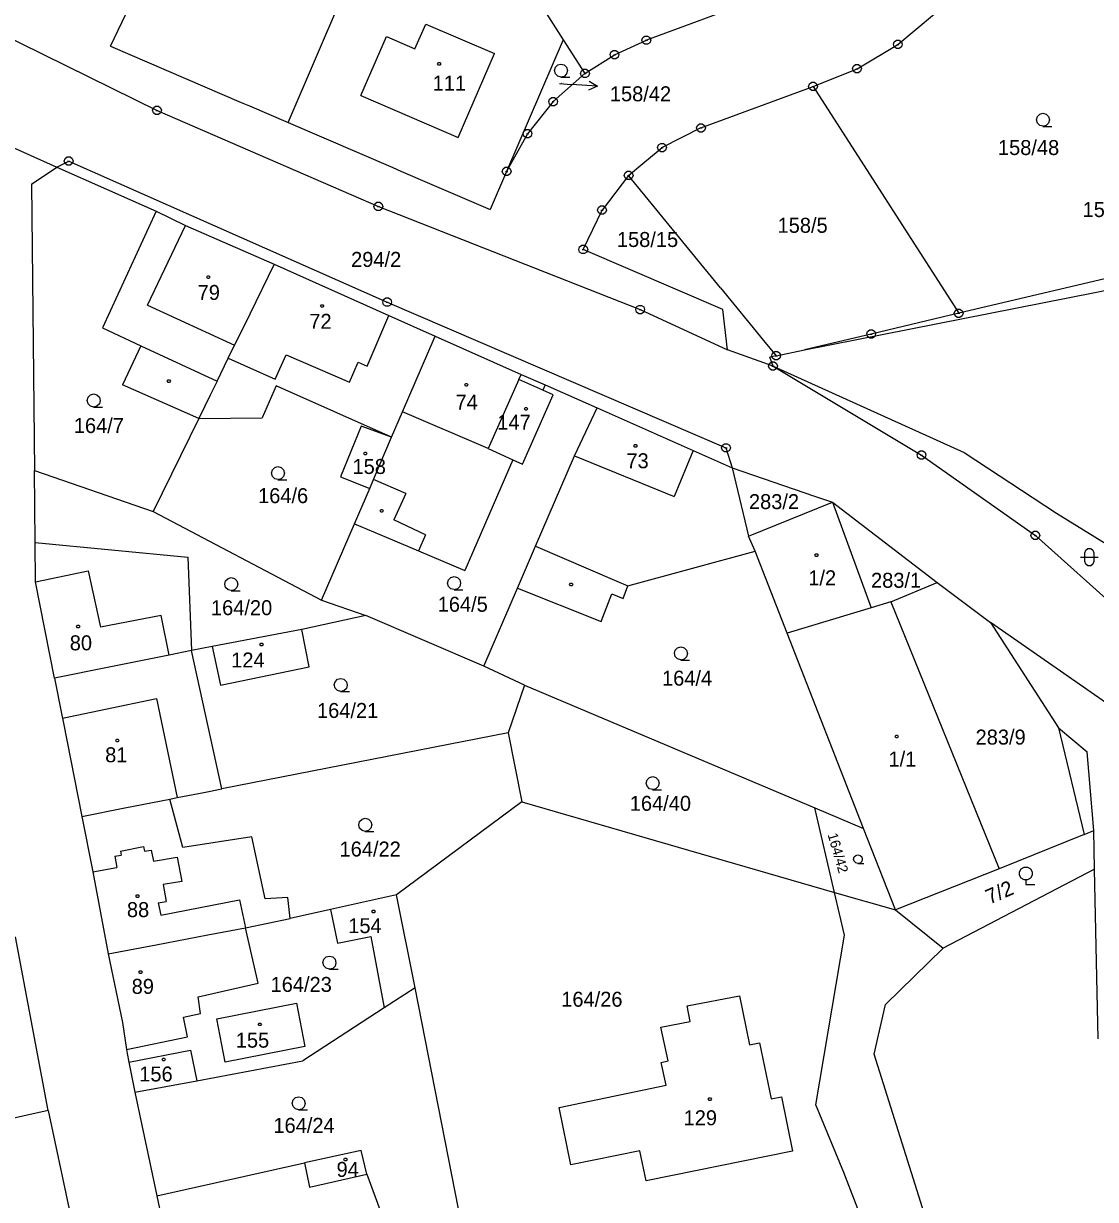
# Model space of a CAD drawing. Extents: x -780000 to -777378, y -1011169 to -1009297.
# Drawn here: x -779372 to -779250.3, y -1010258.1 to -1010124.6 of the extents above; entities that cross this region are included whole.
import ezdxf

# ---------------------------------------------------------------- set-up
doc = ezdxf.new("R2010")
doc.units = 0
for name, color, linetype in [('Default', 7, 'Continuous'), ('KN_HRANICE', 7, 'Continuous'), ('KN_KULTURY', 7, 'Continuous'), ('KN_PARCELY', 7, 'Continuous'), ('KN_SLUCKY', 7, 'Continuous')]:
    doc.layers.add(name, color=color, linetype=linetype)

# ---------------------------------------------------------------- blocks, each defined once
blk = doc.blocks.new('304')
at = {"layer": 'Default'}
blk.add_lwpolyline([(0, 0), (-0.38, 0.1), (-0.65, 0.37), (-0.75, 0.74), (-0.65, 1.11), (-0.38, 1.38), (-0.01, 1.48), (0.36, 1.38), (0.63, 1.11), (0.73, 0.73), (0.63, 0.35), (0.36, 0.08), (-0.02, -0.02), (0.98, -0.02)], dxfattribs=at)
blk = doc.blocks.new('305')
at = {"layer": 'Default'}
blk.add_lwpolyline([(0, 0.53), (-0.19, 0.53), (-0.53, 0.72), (-0.72, 1.06), (-0.72, 1.45), (-0.53, 1.79), (-0.19, 1.98), (0.2, 1.98), (0.54, 1.79), (0.73, 1.45), (0.73, 1.06), (0.54, 0.72), (0.2, 0.53), (0.01, 0.53), (0.01, 0), (1.01, 0)], dxfattribs=at)
blk = doc.blocks.new('316')
at = {"layer": 'Default'}
for points in [[(-0.5, 1.5), (-0.4, 1.79), (-0.15, 1.97), (0.16, 1.97), (0.41, 1.79), (0.51, 1.5), (0.51, 0.5), (0.41, 0.21), (0.16, 0.03), (-0.15, 0.03), (-0.4, 0.21), (-0.5, 0.5), (-0.5, 1.5)], [(-1, 1), (0.27, 1), (1, 1)]]:
    blk.add_lwpolyline(points, dxfattribs=at)
blk = doc.blocks.new('10292')
at = {"layer": 'Default'}
blk.add_line((0, 3), (0, 0), dxfattribs=at)
blk.add_lwpolyline([(-0.5, 2), (0, 3), (0.5, 2)], dxfattribs=at)
blk = doc.blocks.new('402')
at = {"layer": 'Default'}
blk.add_lwpolyline([(0.09, 0.15), (0.18, 0), (0.09, -0.15), (-0.09, -0.15), (-0.18, 0), (-0.09, 0.15), (0.09, 0.15)], dxfattribs=at)
blk = doc.blocks.new('105')
at = {"layer": 'Default'}
blk.add_line((-0.12, 0), (0.12, 0), dxfattribs=at)
blk.add_lwpolyline([(0.15, 0.48), (0.4, 0.3), (0.5, 0.01), (0.4, -0.28), (0.15, -0.46), (-0.16, -0.46), (-0.41, -0.28), (-0.51, 0.01), (-0.41, 0.3), (-0.16, 0.48), (0.15, 0.48)], dxfattribs=at)

msp = doc.modelspace()

# ---------------------------------------------------------------- linework, layer by layer
at = {"layer": 'KN_HRANICE'}
for p, q in [((-779362.17, -1010127.2), (-779340.06, -1010080.85)), ((-779342.01, -1010135.87), (-779327.06, -1010101.1)), ((-779327.06, -1010101.1), (-779310.76, -1010126.49)), ((-779380.8, -1010122.72), (-779356.88, -1010134.5)), ((-779288.77, -1010121.88), (-779301.33, -1010126.54)), ((-779272.77, -1010127.01), (-779268.62, -1010123.54)), ((-779327.61, -1010127.53), (-779326.36, -1010124.72)), ((-779326.36, -1010124.72), (-779318.57, -1010128.06)), ((-779333.75, -1010132.81), (-779330.83, -1010126.13)), ((-779330.83, -1010126.13), (-779327.61, -1010127.53)), ((-779310.76, -1010126.49), (-779317.19, -1010141.44)), ((-779310.76, -1010126.49), (-779308.3, -1010130.32)), ((-779304.94, -1010128.18), (-779301.33, -1010126.54)), ((-779308.3, -1010130.32), (-779304.94, -1010128.18)), ((-779277.41, -1010129.77), (-779272.77, -1010127.01)), ((-779308.3, -1010130.32), (-779311.9, -1010133.51)), ((-779282.4, -1010131.79), (-779277.41, -1010129.77)), ((-779295.13, -1010136.5), (-779282.4, -1010131.79)), ((-779282.4, -1010131.79), (-779265.87, -1010157.54)), ((-779311.9, -1010133.51), (-779314.82, -1010137.15)), ((-779356.88, -1010134.5), (-779331.75, -1010145.42)), ((-779379.75, -1010135.84), (-779368.25, -1010140.93)), ((-779314.82, -1010137.15), (-779317.19, -1010141.44)), ((-779295.13, -1010136.5), (-779299.54, -1010138.73)), ((-779300, -1010139.11), (-779299.54, -1010138.73)), ((-779301.73, -1010140.55), (-779300, -1010139.11)), ((-779371.12, -1010142.88), (-779368.25, -1010140.93)), ((-779368.25, -1010140.93), (-779356.99, -1010145.94)), ((-779317.19, -1010141.44), (-779319.05, -1010145.75)), ((-779303.34, -1010141.89), (-779301.73, -1010140.55)), ((-779371.12, -1010142.88), (-779370.81, -1010175.38)), ((-779303.34, -1010141.89), (-779306.36, -1010145.83)), ((-779292.91, -1010154.64), (-779303.34, -1010141.89)), ((-779331.75, -1010145.42), (-779302.03, -1010157.12)), ((-779356.99, -1010145.94), (-779363.09, -1010159.19)), ((-779356.99, -1010145.94), (-779353.64, -1010147.57)), ((-779308.49, -1010150.3), (-779306.36, -1010145.83)), ((-779353.64, -1010147.57), (-779343.57, -1010151.97)), ((-779225.76, -1010148.05), (-779265.87, -1010157.54)), ((-779292.63, -1010157.12), (-779308.49, -1010150.3)), ((-779283.36, -1010161.68), (-779225.71, -1010150.28)), ((-779343.57, -1010151.97), (-779346.34, -1010157.62)), ((-779343.57, -1010151.97), (-779330.56, -1010157.78)), ((-779292.91, -1010154.64), (-779288.01, -1010160.63)), ((-779302.03, -1010157.12), (-779292.12, -1010161.67)), ((-779292.12, -1010161.67), (-779292.63, -1010157.12)), ((-779265.87, -1010157.54), (-779275.8, -1010159.89)), ((-779346.34, -1010157.62), (-779348.07, -1010161.15)), ((-779330.56, -1010157.78), (-779325.31, -1010160.13)), ((-779363.09, -1010159.19), (-779358.72, -1010161.22)), ((-779329.01, -1010168.72), (-779325.31, -1010160.13)), ((-779325.31, -1010160.13), (-779315.53, -1010164.48)), ((-779275.8, -1010159.89), (-779283.36, -1010161.68)), ((-779358.72, -1010161.22), (-779360.82, -1010165.67)), ((-779348.79, -1010162.63), (-779348.07, -1010161.15)), ((-779288.01, -1010160.63), (-779286.59, -1010162.36)), ((-779350.07, -1010165.25), (-779348.79, -1010162.63)), ((-779286.95, -1010163.54), (-779292.12, -1010161.67)), ((-779286.59, -1010162.36), (-779287.32, -1010162.52)), ((-779286.95, -1010163.54), (-779287.32, -1010162.52)), ((-779286.59, -1010162.36), (-779283.36, -1010161.68)), ((-779286.95, -1010163.54), (-779270.09, -1010173.63)), ((-779286.95, -1010163.54), (-779265.26, -1010173.35)), ((-779350.07, -1010165.25), (-779350.37, -1010165.85)), ((-779315.79, -1010165.07), (-779319.28, -1010172.9)), ((-779313.09, -1010166.28), (-779315.79, -1010165.07)), ((-779315.53, -1010164.48), (-779312.82, -1010165.66)), ((-779352.15, -1010169.47), (-779360.82, -1010165.67)), ((-779350.86, -1010166.85), (-779352.15, -1010169.47)), ((-779350.37, -1010165.85), (-779350.86, -1010166.85)), ((-779343.34, -1010165.79), (-779344.96, -1010169.41)), ((-779330.25, -1010171.61), (-779343.34, -1010165.79)), ((-779315.38, -1010174.67), (-779311.89, -1010166.81)), ((-779312.82, -1010165.66), (-779313.09, -1010166.28)), ((-779311.89, -1010166.81), (-779313.09, -1010166.28)), ((-779312.82, -1010165.66), (-779306.92, -1010168.28)), ((-779352.15, -1010169.47), (-779357.33, -1010180.05)), ((-779352.15, -1010169.47), (-779344.96, -1010169.41)), ((-779330.25, -1010171.61), (-779329.01, -1010168.72)), ((-779309.48, -1010173.73), (-779306.92, -1010168.28)), ((-779306.92, -1010168.28), (-779296.03, -1010173.11)), ((-779332.31, -1010176.42), (-779330.25, -1010171.61)), ((-779319.28, -1010172.9), (-779316.5, -1010174.16)), ((-779296.03, -1010173.11), (-779291.6, -1010175.07)), ((-779265.26, -1010173.35), (-779254.75, -1010180.24)), ((-779316.5, -1010174.16), (-779321.95, -1010186.72)), ((-779316.5, -1010174.16), (-779315.38, -1010174.67)), ((-779313.9, -1010183.97), (-779309.48, -1010173.73)), ((-779270.09, -1010173.63), (-779257.16, -1010182.76)), ((-779370.73, -1010183.55), (-779370.81, -1010175.38)), ((-779370.81, -1010175.38), (-779357.33, -1010180.05)), ((-779291.6, -1010175.07), (-779289.74, -1010182.83)), ((-779334.46, -1010181.43), (-779332.74, -1010177.43)), ((-779332.74, -1010177.43), (-779332.31, -1010176.42)), ((-779357.33, -1010180.05), (-779338.22, -1010190.12)), ((-779289.74, -1010182.83), (-779280.19, -1010178.98)), ((-779280.19, -1010178.98), (-779268.33, -1010188.11)), ((-779280.19, -1010178.98), (-779275.82, -1010190.98)), ((-779254.75, -1010180.24), (-779242.9, -1010187.56)), ((-779338.22, -1010190.12), (-779334.46, -1010181.43)), ((-779334.46, -1010181.43), (-779330.86, -1010182.95)), ((-779288.98, -1010184.55), (-779289.74, -1010182.83)), ((-779257.16, -1010182.76), (-779242.79, -1010195.65)), ((-779370.69, -1010188.04), (-779370.73, -1010183.55)), ((-779370.73, -1010183.55), (-779353.39, -1010185.24)), ((-779330.86, -1010182.95), (-779327.18, -1010184.51)), ((-779315.95, -1010188.73), (-779313.9, -1010183.97)), ((-779353.39, -1010185.24), (-779352.97, -1010195.83)), ((-779327.18, -1010184.51), (-779321.95, -1010186.72)), ((-779303.42, -1010188.49), (-779288.98, -1010184.55)), ((-779285.33, -1010193.87), (-779288.98, -1010184.55)), ((-779368.51, -1010198.95), (-779370.69, -1010188.04)), ((-779273.57, -1010190.29), (-779268.33, -1010188.11)), ((-779268.33, -1010188.11), (-779262.24, -1010192.63)), ((-779319.77, -1010197.59), (-779315.95, -1010188.73)), ((-779315.95, -1010188.73), (-779306.46, -1010192.53)), ((-779306.46, -1010192.53), (-779305.24, -1010189.37)), ((-779305.24, -1010189.37), (-779303.95, -1010189.91)), ((-779303.95, -1010189.91), (-779303.42, -1010188.49)), ((-779338.22, -1010190.12), (-779333.16, -1010191.86)), ((-779273.57, -1010190.29), (-779275.82, -1010190.98)), ((-779273.57, -1010190.29), (-779261.29, -1010220.59)), ((-779333.16, -1010191.86), (-779340.44, -1010193.45)), ((-779319.77, -1010197.59), (-779333.16, -1010191.86)), ((-779275.82, -1010190.98), (-779285.33, -1010193.87)), ((-779340.44, -1010193.45), (-779350.63, -1010195.35)), ((-779339.6, -1010197.69), (-779340.44, -1010193.45)), ((-779262.24, -1010192.63), (-779254.52, -1010204.61)), ((-779246.71, -1010203.46), (-779262.24, -1010192.63)), ((-779276.66, -1010216.01), (-779285.33, -1010193.87)), ((-779352.97, -1010195.83), (-779355.52, -1010196.34)), ((-779350.63, -1010195.35), (-779352.97, -1010195.83)), ((-779349.54, -1010211.54), (-779352.97, -1010195.83)), ((-779350.63, -1010195.35), (-779349.69, -1010199.77)), ((-779355.52, -1010196.34), (-779362.33, -1010197.71)), ((-779315.16, -1010199.77), (-779319.77, -1010197.59)), ((-779362.33, -1010197.71), (-779368.51, -1010198.95)), ((-779349.69, -1010199.77), (-779339.6, -1010197.69)), ((-779315.16, -1010199.77), (-779317, -1010205.16)), ((-779315.16, -1010199.77), (-779282.2, -1010213.67)), ((-779317, -1010205.16), (-779349.54, -1010211.54)), ((-779317, -1010205.16), (-779315.47, -1010213.01)), ((-779254.52, -1010204.61), (-779251.62, -1010216.72)), ((-779354.59, -1010212.5), (-779351.55, -1010211.93)), ((-779351.55, -1010211.93), (-779349.54, -1010211.54)), ((-779360.52, -1010213.7), (-779355.42, -1010212.7)), ((-779355.42, -1010212.7), (-779354.59, -1010212.5)), ((-779353.94, -1010218.2), (-779355.42, -1010212.7)), ((-779315.47, -1010213.01), (-779329.68, -1010223.56)), ((-779315.47, -1010213.01), (-779279.96, -1010223.28)), ((-779365.42, -1010214.66), (-779360.52, -1010213.7)), ((-779365.42, -1010214.66), (-779364.16, -1010220.93)), ((-779282.2, -1010213.67), (-779276.66, -1010216.01)), ((-779279.96, -1010223.28), (-779282.2, -1010213.67)), ((-779273.03, -1010225.28), (-779276.66, -1010216.01)), ((-779251.62, -1010216.72), (-779250.54, -1010216.27)), ((-779250.45, -1010220.64), (-779250.54, -1010216.27)), ((-779346.13, -1010216.99), (-779353.94, -1010218.2)), ((-779344.62, -1010224.02), (-779346.13, -1010216.99)), ((-779251.62, -1010216.72), (-779261.29, -1010220.59)), ((-779364.16, -1010220.93), (-779362.43, -1010230.27)), ((-779261.29, -1010220.59), (-779273.03, -1010225.28)), ((-779250.45, -1010220.64), (-779267.64, -1010229.61)), ((-779250.04, -1010239.9), (-779250.45, -1010220.64)), ((-779342.02, -1010223.87), (-779344.62, -1010224.02)), ((-779341.78, -1010226.26), (-779342.02, -1010223.87)), ((-779329.68, -1010223.56), (-779337.17, -1010225.23)), ((-779327.59, -1010234.13), (-779329.68, -1010223.56)), ((-779279.96, -1010223.28), (-779273.03, -1010225.28)), ((-779278.82, -1010228.15), (-779279.96, -1010223.28)), ((-779337.17, -1010225.23), (-779341.78, -1010226.26)), ((-779273.03, -1010225.28), (-779267.64, -1010229.61)), ((-779346.83, -1010227.29), (-779341.78, -1010226.26)), ((-779369.26, -1010248.05), (-779372.96, -1010228.31)), ((-779356.99, -1010229.23), (-779351.1, -1010228.1)), ((-779351.1, -1010228.1), (-779346.83, -1010227.29)), ((-779282.1, -1010247.39), (-779278.82, -1010228.15)), ((-779362.43, -1010230.27), (-779356.99, -1010229.23)), ((-779274.18, -1010236), (-779267.64, -1010229.61)), ((-779362.43, -1010230.27), (-779360.81, -1010238.06)), ((-779327.59, -1010234.13), (-779331.1, -1010236.4)), ((-779321.68, -1010264.11), (-779327.59, -1010234.13)), ((-779296.68, -1010236.16), (-779290.77, -1010235.01)), ((-779296.34, -1010237.93), (-779296.68, -1010236.16)), ((-779290.77, -1010235.01), (-779289.63, -1010240.6)), ((-779275.45, -1010241.64), (-779274.18, -1010236)), ((-779331.1, -1010236.4), (-779340.34, -1010242.39)), ((-779360.81, -1010238.06), (-779360.33, -1010241.1)), ((-779299.67, -1010238.58), (-779296.34, -1010237.93)), ((-779298.86, -1010242.42), (-779299.67, -1010238.58)), ((-779360.33, -1010241.1), (-779360.26, -1010241.57)), ((-779360.26, -1010241.57), (-779360.07, -1010242.55)), ((-779289.63, -1010240.6), (-779288.47, -1010240.36)), ((-779288.47, -1010240.36), (-779287.16, -1010246.73)), ((-779248.83, -1010326.61), (-779275.45, -1010241.64)), ((-779360.07, -1010242.55), (-779359.42, -1010245.98)), ((-779352.38, -1010244.66), (-779340.34, -1010242.39)), ((-779299.63, -1010242.58), (-779298.86, -1010242.42)), ((-779299.09, -1010245.15), (-779299.63, -1010242.58)), ((-779359.42, -1010245.98), (-779352.38, -1010244.66)), ((-779311.24, -1010247.7), (-779299.09, -1010245.15)), ((-779359.42, -1010245.98), (-779356.9, -1010257.72)), ((-779287.16, -1010246.73), (-779285.99, -1010246.49)), ((-779285.99, -1010246.49), (-779284.72, -1010252.66)), ((-779369.26, -1010248.05), (-779389.34, -1010252.55)), ((-779369.26, -1010248.05), (-779366.85, -1010259.23)), ((-779309.89, -1010254.22), (-779311.24, -1010247.7)), ((-779278.89, -1010255.08), (-779282.1, -1010247.39)), ((-779333.7, -1010252.59), (-779340.13, -1010253.99)), ((-779333.07, -1010255.29), (-779333.7, -1010252.59)), ((-779302.06, -1010252.64), (-779309.89, -1010254.22)), ((-779301.34, -1010256.04), (-779302.06, -1010252.64)), ((-779284.72, -1010252.66), (-779301.34, -1010256.04)), ((-779356.9, -1010257.72), (-779340.13, -1010253.99)), ((-779340.13, -1010253.99), (-779339.57, -1010256.76)), ((-779339.57, -1010256.76), (-779333.07, -1010255.29)), ((-779333.07, -1010255.29), (-779329.22, -1010265.58)), ((-779276.95, -1010260.2), (-779278.89, -1010255.08)), ((-779356.9, -1010257.72), (-779355.68, -1010263.39))]:
    msp.add_line(p, q, dxfattribs=at)
for points in [[(-779362.17, -1010127.2), (-779347.32, -1010133.59), (-779346.4, -1010133.98), (-779342.01, -1010135.87)], [(-779333.75, -1010132.81), (-779322.68, -1010137.57), (-779318.57, -1010128.06)], [(-779342.01, -1010135.87), (-779330.11, -1010140.99), (-779329.19, -1010141.39), (-779325.94, -1010142.79), (-779319.05, -1010145.75)], [(-779330.25, -1010171.61), (-779333.7, -1010170.34), (-779336.07, -1010176.09), (-779332.74, -1010177.43)], [(-779291.6, -1010175.07), (-779282.25, -1010178.28), (-779280.19, -1010178.98)], [(-779368.51, -1010198.95), (-779367.68, -1010203.17), (-779367.63, -1010203.52)], [(-779367.63, -1010203.52), (-779367.55, -1010203.87), (-779365.42, -1010214.66)], [(-779337.17, -1010225.23), (-779336.4, -1010229.03), (-779332.59, -1010228.29), (-779331.1, -1010236.4)], [(-779360.33, -1010241.1), (-779353.42, -1010239.67), (-779353.88, -1010237.43), (-779351.94, -1010237.03), (-779352.2, -1010235.13), (-779345.41, -1010233.6), (-779346.83, -1010227.29)], [(-779360.07, -1010242.55), (-779353.08, -1010241.18), (-779352.38, -1010244.66)]]:
    msp.add_lwpolyline(points, dxfattribs=at)
msp.add_lwpolyline([(-779350.1, -1010237.63), (-779341.04, -1010235.87), (-779340.09, -1010240.76), (-779349.15, -1010242.54)], close=True, dxfattribs=at)
at = {"layer": 'KN_PARCELY'}
msp.add_line((-779311.2, -1010131.45), (-779309.85, -1010131.55), dxfattribs=at)
at = {"layer": 'KN_SLUCKY'}
for p, q in [((-779368.25, -1010140.93), (-779366.91, -1010140.27)), ((-779366.91, -1010140.27), (-779330.75, -1010156.28)), ((-779357.95, -1010156.63), (-779353.64, -1010147.57)), ((-779357.95, -1010156.63), (-779348.07, -1010161.15)), ((-779330.75, -1010156.28), (-779292.29, -1010172.82)), ((-779333.01, -1010163.53), (-779330.56, -1010157.78)), ((-779358.72, -1010161.22), (-779350.07, -1010165.25)), ((-779334.03, -1010163.08), (-779333.01, -1010163.53)), ((-779315.79, -1010165.07), (-779315.53, -1010164.48)), ((-779319.28, -1010172.9), (-779329.01, -1010168.72)), ((-779296.03, -1010173.11), (-779298.16, -1010178.34)), ((-779292.29, -1010172.82), (-779291.6, -1010175.07)), ((-779309.48, -1010173.73), (-779298.16, -1010178.34)), ((-779328.64, -1010178), (-779332.31, -1010176.42)), ((-779328.64, -1010178), (-779329.98, -1010180.98)), ((-779326.39, -1010182.67), (-779329.98, -1010180.98)), ((-779326.39, -1010182.67), (-779327.18, -1010184.51)), ((-779313.9, -1010183.97), (-779304.69, -1010187.94)), ((-779370.69, -1010188.04), (-779364.7, -1010186.76)), ((-779364.7, -1010186.76), (-779363.31, -1010193.19)), ((-779304.69, -1010187.94), (-779303.42, -1010188.49)), ((-779356.41, -1010191.83), (-779363.31, -1010193.19)), ((-779355.52, -1010196.34), (-779356.41, -1010191.83)), ((-779362.74, -1010202.49), (-779356.94, -1010201.26)), ((-779356.94, -1010201.26), (-779354.59, -1010212.5)), ((-779367.63, -1010203.52), (-779362.74, -1010202.49)), ((-779254.52, -1010204.61), (-779251.28, -1010207.31)), ((-779250.54, -1010216.27), (-779251.28, -1010207.31)), ((-779361.03, -1010218.61), (-779358.43, -1010218.07)), ((-779361.03, -1010218.61), (-779360.95, -1010219.06)), ((-779358.43, -1010218.07), (-779358.32, -1010218.61)), ((-779358.32, -1010218.61), (-779357.53, -1010218.47)), ((-779357.53, -1010218.47), (-779357.27, -1010219.74)), ((-779361.69, -1010219.18), (-779360.95, -1010219.06)), ((-779361.69, -1010219.18), (-779361.45, -1010220.46)), ((-779357.27, -1010219.74), (-779354.61, -1010219.28)), ((-779354.61, -1010219.28), (-779354.07, -1010222.04)), ((-779364.16, -1010220.93), (-779361.45, -1010220.46)), ((-779354.07, -1010222.04), (-779356.19, -1010222.38)), ((-779356.19, -1010222.38), (-779355.84, -1010224.3)), ((-779356.77, -1010224.47), (-779355.84, -1010224.3)), ((-779356.45, -1010225.88), (-779347.53, -1010224.13)), ((-779347.53, -1010224.13), (-779346.83, -1010227.29)), ((-779356.77, -1010224.47), (-779356.45, -1010225.88))]:
    msp.add_line(p, q, dxfattribs=at)
msp.add_lwpolyline([(-779348.79, -1010162.63), (-779343.48, -1010165.02), (-779342.22, -1010162.27), (-779335.04, -1010165.34), (-779334.03, -1010163.08)], dxfattribs=at)

# ---------------------------------------------------------------- block references
at = {"layer": 'KN_KULTURY'}
for name, p in [('402', (-779324.85, -1010129.2)), ('304', (-779311.01, -1010130.72)), ('304', (-779256.29, -1010136.31)), ('402', (-779351.06, -1010153.44)), ('402', (-779338.13, -1010156.71)), ('402', (-779355.54, -1010165.23)), ('402', (-779321.77, -1010165.65)), ('304', (-779364.06, -1010168.18)), ('402', (-779315, -1010168.37)), ('402', (-779333.24, -1010173.47)), ('402', (-779302.56, -1010172.59)), ('304', (-779343.14, -1010176.42)), ('402', (-779331.38, -1010179.95)), ('316', (-779251.04, -1010186.22)), ('402', (-779282.01, -1010184.99)), ('304', (-779348.44, -1010189.02)), ('304', (-779323.14, -1010188.91)), ('402', (-779309.86, -1010188.31)), ('402', (-779365.83, -1010193.09)), ('402', (-779345.02, -1010195.14)), ('304', (-779297.4, -1010196.88)), ('304', (-779336.02, -1010200.47)), ('402', (-779272.91, -1010205.57)), ('402', (-779361.39, -1010206.03)), ('304', (-779300.6, -1010211.61)), ('304', (-779333.23, -1010216.35)), ('305', (-779258.25, -1010222.38)), ('402', (-779359.1, -1010223.72)), ('402', (-779332.31, -1010225.46)), ('304', (-779337.3, -1010231.99)), ('402', (-779358.76, -1010232.33)), ('402', (-779345.21, -1010238.26)), ('402', (-779356.13, -1010242.24)), ('304', (-779340.79, -1010247.96)), ('402', (-779294.12, -1010246.74)), ('402', (-779335.49, -1010253.62))]:
    msp.add_blockref(name, p, dxfattribs=at)
at = {"layer": 'KN_KULTURY', "xscale": 0.67, "yscale": 0.67}
msp.add_blockref('304', (-779277.3, -1010220), dxfattribs=at)
at = {"layer": 'KN_PARCELY'}
for p in [(-779301.33, -1010126.54), (-779272.77, -1010127.01), (-779304.94, -1010128.18), (-779277.41, -1010129.77), (-779308.3, -1010130.32), (-779282.4, -1010131.79), (-779311.9, -1010133.51), (-779356.88, -1010134.5), (-779295.13, -1010136.5), (-779314.82, -1010137.15), (-779299.54, -1010138.73), (-779366.91, -1010140.27), (-779317.19, -1010141.44), (-779303.34, -1010141.89), (-779331.75, -1010145.42), (-779306.36, -1010145.83), (-779308.49, -1010150.3), (-779330.75, -1010156.28), (-779302.03, -1010157.12), (-779265.87, -1010157.54), (-779275.8, -1010159.89), (-779286.59, -1010162.36), (-779286.95, -1010163.54), (-779292.29, -1010172.82), (-779270.09, -1010173.63), (-779257.16, -1010182.76)]:
    msp.add_blockref('105', p, dxfattribs=at)
at = {"layer": 'KN_PARCELY', "rotation": -94.20487900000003}
msp.add_blockref('10292', (-779309.85, -1010131.55), dxfattribs=at)

# ---------------------------------------------------------------- texts
at = {"layer": 'KN_PARCELY'}
for s, height, p in [('111', 1.7, (-779325.59, -1010132.25)), ('158/42', 0.1, (-779311.18, -1010131.45)), ('158/42', 1.7, (-779305.47, -1010133.47)), ('158/48', 1.7, (-779261.41, -1010139.57)), ('158/35', 1.7, (-779251.8, -1010146.61)), ('158/5', 1.7, (-779286.43, -1010148.4)), ('158/15', 1.7, (-779304.67, -1010150.01)), ('294/2', 1.7, (-779334.85, -1010152.27)), ('79', 1.7, (-779352.27, -1010156.02)), ('72', 1.7, (-779339.59, -1010159.3)), ('74', 1.7, (-779322.99, -1010168.47)), ('164/7', 1.7, (-779366.33, -1010171.13)), ('147', 1.7, (-779318.25, -1010170.75)), ('73', 1.7, (-779303.59, -1010175.13)), ('158', 1.7, (-779334.69, -1010175.78)), ('164/6', 1.7, (-779345.41, -1010179.09)), ('283/2', 1.7, (-779289.68, -1010179.77)), ('1/2', 1.7, (-779282.94, -1010188.42)), ('283/1', 1.7, (-779275.82, -1010188.7)), ('164/20', 1.7, (-779350.76, -1010191.81)), ('164/5', 1.7, (-779325.02, -1010191.42)), ('80', 1.7, (-779366.79, -1010195.8)), ('124', 1.7, (-779348.46, -1010197.75)), ('164/4', 1.7, (-779299.55, -1010199.81)), ('164/21', 1.7, (-779338.72, -1010203.48)), ('283/9', 1.7, (-779263.95, -1010206.5)), ('81', 1.7, (-779362.77, -1010208.51)), ('1/1', 1.7, (-779273.84, -1010209)), ('164/40', 1.7, (-779303.21, -1010214.02)), ('164/22', 1.7, (-779336.16, -1010219.21)), ('88', 1.7, (-779360.3, -1010226.09)), ('154', 1.7, (-779335.17, -1010227.91)), ('89', 1.7, (-779359.76, -1010234.8)), ('164/23', 1.7, (-779343.99, -1010234.58)), ('164/26', 1.7, (-779310.99, -1010236.26)), ('155', 1.7, (-779347.94, -1010240.91)), ('156', 1.7, (-779358.9, -1010244.75)), ('129', 1.7, (-779297.1, -1010249.72)), ('164/24', 1.7, (-779343.67, -1010250.58)), ('94', 1.7, (-779336.5, -1010255.58))]:
    msp.add_text(s, height=height, dxfattribs=at).set_placement(p)
for s, height, rotation, p in [('164/42', 1.14, 286.135, (-779280.76, -1010216.72)), ('7/2', 1.7, 23.262, (-779262.37, -1010224.67))]:
    msp.add_text(s, height=height, rotation=rotation, dxfattribs=at).set_placement(p)

doc.saveas('drawing.dxf')
